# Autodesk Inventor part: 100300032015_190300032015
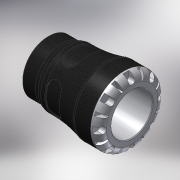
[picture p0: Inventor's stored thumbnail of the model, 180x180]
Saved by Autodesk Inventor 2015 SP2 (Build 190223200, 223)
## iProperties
Created: 2016-12
Part Number: 100300032015_190300032015
Material: PVC-Piping
Description: PLASSON FEMALE ADAPTOR 32X1.1/2" SERIES 1
Document SubType Name: Modeling
Designer: KIM
Mass: 137.779 g
Surface Area: 303.415 cm^2
Volume: 98.4137 cm^3
Density: 1.4 g/cm^3
Appearance: Black Cast
Author: KIM
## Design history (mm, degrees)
derived "1003.ipt"
feature "Solid1::1003.ipt"
tag "TaggingFeature1"
body "Solid1"
other parameters: "d0" = 95, "d1" = 22.68, "d2" = 32, "d4" = 58, "d6" = 54, "d8" = 49.3, "d13" = 7.2, "d14" = 7.2, "d15" = 0, "d17" = 360 deg, "d19" = 8 deg, "d20" = 0.64, "d21" = 0.64, "d22" = 8 deg, "d24" = 0, "d26" = 360 deg, "d32" = 5.8, "d33" = 5.8, "d39" = 1.34535, "d42" = 44.845, "d43" = 47.56, "d46" = 2.66667, "d47" = 24, "d48" = 42.60275, "d50" = 5.61, "d51" = 0.58, "d54" = 11.2, "d55" = 7.04, "d57" = 14.112, "d58" = 0, "d68" = 360 deg, "d72" = 0.64, "d74" = 0, "d76" = 9.52, "d_" = 32, "E_" = 58, "H_" = 95, "l_" = 54, "Rp" = 44.845, "l_2" = 24, "d9" = 9, "d11" = 58, "d49" = 17
